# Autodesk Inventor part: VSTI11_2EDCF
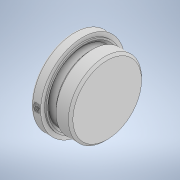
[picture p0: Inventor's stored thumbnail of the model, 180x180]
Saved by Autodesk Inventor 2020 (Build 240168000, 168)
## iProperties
Created: 2019-12
Part Number: VSTI11_2EDCF
Material: Generico
Description: STEP AP203
Document SubType Name: Modeling
Designer: carlo
Density: 1 g/cm^3
Appearance: Default
DataBaseUnit: MM
Title: p:/temp/worker_151/temp/exporttempdir_6952_305_TSvW2/format_0/EO Verschluss-Stopfen fuer Einschraubloecher VSTI11_2EDCF.stp
Revision Number: NONE
Sending System: PARTsolutions
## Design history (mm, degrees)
feature "_EO Verschluss-Stopfen fuer Einschraubloecher VSTI11_2EDCF"
node "Piano di lavoro1"
node "Piano di lavoro2"
node "Asse di lavoro1"
node "Solido1"
other parameters: "d0" = 0, "d1" = 0
